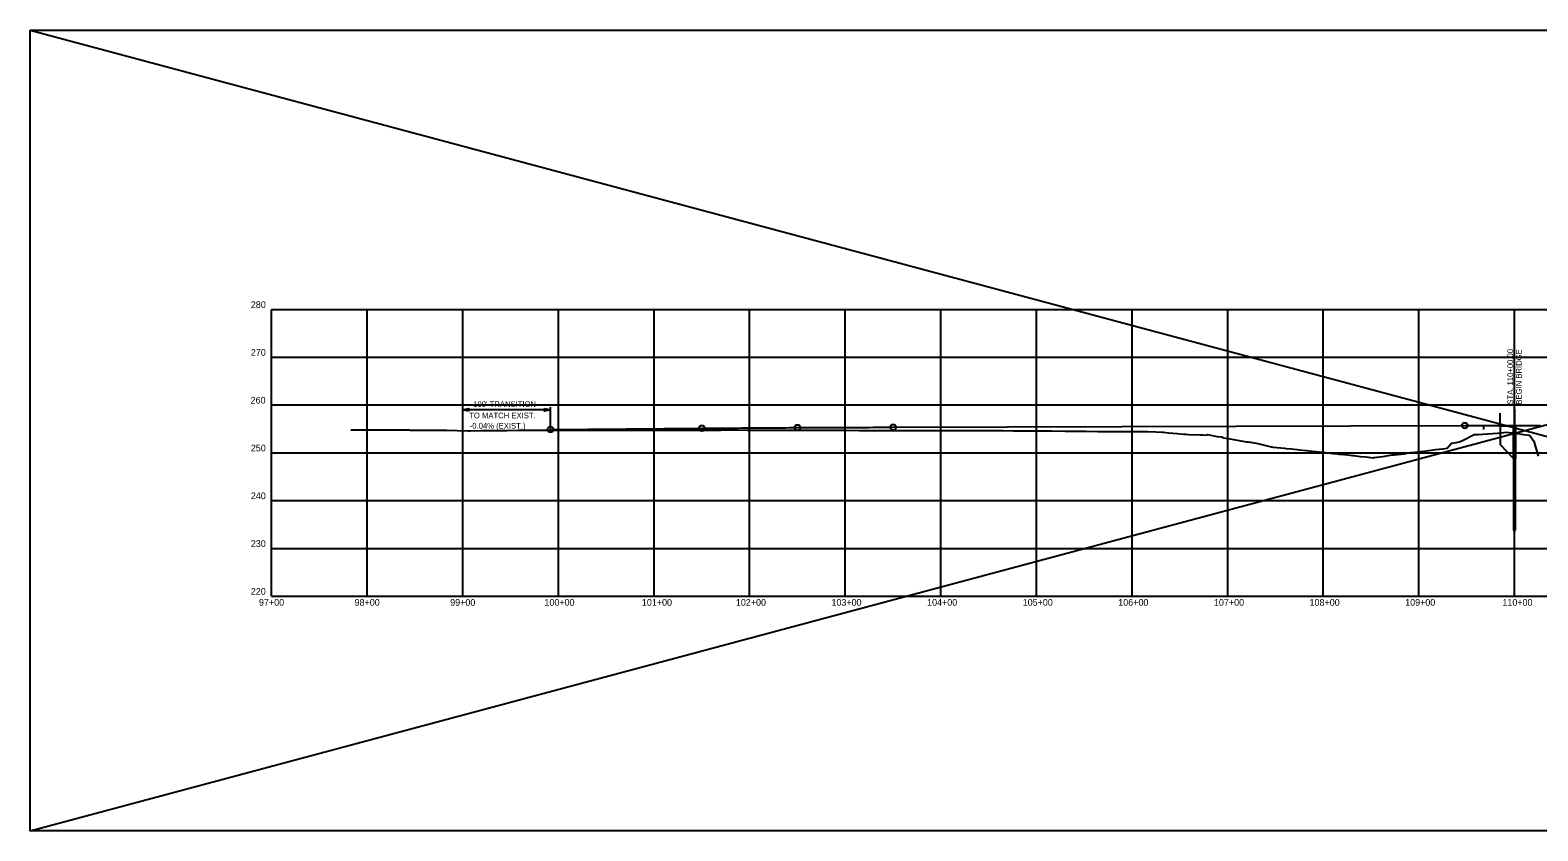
# Model space of a CAD drawing. Extents: x 1930770 to 1938778, y 596900 to 600561.
# Drawn here: x 1935653 to 1937230, y 598329 to 599167 of the extents above; entities that cross this region are included whole.
import ezdxf

# ---------------------------------------------------------------- set-up
doc = ezdxf.new("R2010")
doc.units = 0
for name, color, linetype in [('B_Centerline', 7, 'Continuous'), ('B_Pr_Beam_Line', 7, 'Continuous'), ('B_Pr_Columns', 7, 'Continuous'), ('B_Pr_Deck', 7, 'Continuous'), ('B_Pr_Rail', 7, 'Continuous'), ('Default', 7, 'Continuous'), ('S_CROSS_DRAIN_ANNOT', 7, 'Continuous'), ('S_DROP_INLET_ANNOT', 7, 'Continuous'), ('S_ELECTRIC_UTILITIES_ANNOT', 7, 'Continuous'), ('S_GAS_UTILITIES_ANNOT', 7, 'Continuous'), ('S_HIST_HIGH_WATER_ANNOT', 7, 'Continuous'), ('S_STORM_SEWER_ANNOT', 7, 'Continuous'), ('S_TELEPHONE_UTILITIES_ANNOT', 7, 'Continuous'), ('S_UTILITY_POLE_ANNOT', 7, 'Continuous'), ('S_WATER_UTILITIES_ANNOT', 7, 'Continuous')]:
    doc.layers.add(name, color=color, linetype=linetype)

msp = doc.modelspace()

# ---------------------------------------------------------------- linework, layer by layer
at = {"layer": 'B_Centerline'}
msp.add_line((1937205.2, 598631.1), (1937205.2, 598767.6), dxfattribs=at)
at = {"layer": 'B_Pr_Beam_Line'}
msp.add_line((1937204.7, 598748), (1937204.7, 598736.3), dxfattribs=at)
at = {"layer": 'B_Pr_Columns'}
for p, q in [((1937206.1, 598718.8), (1937204.4, 598718.8)), ((1937204.4, 598643.5), (1937204.4, 598718.8)), ((1937206.1, 598718.8), (1937204.4, 598718.8)), ((1937206.1, 598643.5), (1937206.1, 598718.8))]:
    msp.add_line(p, q, dxfattribs=at)
at = {"layer": 'B_Pr_Deck'}
msp.add_line((1937190.2, 598752.4), (1937205.2, 598752.7), dxfattribs=at)
msp.add_lwpolyline([(1937190.2, 598752.4), (1937190.2, 598733.4), (1937203.7, 598718.8)], dxfattribs=at)
at = {"layer": 'B_Pr_Rail'}
msp.add_line((1937205.2, 598770), (1937205.2, 598753.1), dxfattribs=at)
at = {"layer": 'Default'}
msp.add_line((1937205.2, 598643.5), (1937206.2, 598643.5), dxfattribs=at)
msp.add_lwpolyline([(1937203.9, 598643.5), (1937205, 598643.5), (1937205.2, 598644.9), (1937205, 598642.2), (1937205.2, 598643.5)], dxfattribs=at)
at = {"layer": 'S_CROSS_DRAIN_ANNOT'}
for p, q in [((1935905.2, 598574.6), (1935905.2, 598874.6)), ((1937105.2, 598824.6), (1937105.2, 598826.1)), ((1937105.2, 598824.6), (1937105.2, 598825.8)), ((1935905.2, 598574.6), (1938605.2, 598574.6))]:
    msp.add_line(p, q, dxfattribs=at)
msp.add_lwpolyline([(1935652.7, 599166.8), (1938778.1, 599166.8), (1938778.1, 598329.1), (1935652.7, 598329.1)], close=True, dxfattribs=at)
at = {"layer": 'S_ELECTRIC_UTILITIES_ANNOT'}
for p, q in [((1937205.2, 598782.6), (1937205.2, 598841.8)), ((1937205.2, 598752.6), (1937205.2, 598782.6))]:
    msp.add_line(p, q, dxfattribs=at)
for centre in [(1936196.8, 598749.1), (1936355.2, 598750.3), (1936455.2, 598751), (1936555.2, 598751.3), (1937153.2, 598753.1)]:
    msp.add_circle(centre, 3, dxfattribs=at)
at = {"layer": 'S_GAS_UTILITIES_ANNOT'}
msp.add_lwpolyline([(1937203.7, 598749.1), (1937203.7, 598718.8), (1937206.7, 598718.8), (1937206.7, 598752.7), (1937204.2, 598752.7), (1937204.2, 598749.1)], close=True, dxfattribs=at)
for points in [[(1937203.7, 598718.8), (1937206.7, 598718.8)], [(1937203.7, 598718.8), (1937206.7, 598718.8), (1937206.7, 598718.8)], [(1937203.7, 598718.8), (1937206.7, 598718.8), (1937206.7, 598718.8)]]:
    msp.add_lwpolyline(points, dxfattribs=at)
at = {"layer": 'S_HIST_HIGH_WATER_ANNOT'}
for p, q in [((1936196.8, 598749.1), (1936355.2, 598750.3)), ((1936555.2, 598751.3), (1937153.2, 598753.1))]:
    msp.add_line(p, q, dxfattribs=at)
for points in [[(1936355.2, 598750.3), (1936359.4, 598750.3), (1936363.6, 598750.3), (1936367.7, 598750.4), (1936371.9, 598750.4), (1936376.1, 598750.4), (1936380.2, 598750.5), (1936384.4, 598750.5), (1936388.6, 598750.5), (1936392.7, 598750.5), (1936396.9, 598750.6), (1936401.1, 598750.6), (1936405.2, 598750.6), (1936409.4, 598750.7), (1936413.6, 598750.7), (1936417.7, 598750.7), (1936421.9, 598750.7), (1936426.1, 598750.8), (1936430.2, 598750.8), (1936434.4, 598750.8), (1936438.6, 598750.8), (1936442.7, 598750.8), (1936446.9, 598750.9), (1936451.1, 598750.9), (1936459.4, 598750.9), (1936463.6, 598751), (1936467.7, 598751), (1936471.9, 598751), (1936476.1, 598751), (1936480.2, 598751), (1936484.4, 598751.1), (1936488.6, 598751.1), (1936492.7, 598751.1), (1936496.9, 598751.1), (1936501.1, 598751.1), (1936505.2, 598751.2), (1936509.4, 598751.2), (1936513.6, 598751.2), (1936517.7, 598751.2), (1936521.9, 598751.2), (1936526.1, 598751.2), (1936530.2, 598751.2), (1936534.4, 598751.3), (1936538.6, 598751.3), (1936542.7, 598751.3), (1936546.9, 598751.3), (1936551.1, 598751.3), (1936555.2, 598751.3)], [(1937153.2, 598753.1), (1937157.4, 598753.1), (1937161.6, 598753.1), (1937165.7, 598753.2), (1937169.9, 598753.2), (1937174.1, 598753.2), (1937178.2, 598753.2), (1937182.4, 598753.2), (1937186.6, 598753.2), (1937190.7, 598753.2), (1937194.9, 598753.2), (1937199.1, 598753.2), (1937203.2, 598753.2), (1937207.4, 598753.2), (1937211.6, 598753.2), (1937215.7, 598753.3), (1937219.9, 598753.3), (1937224.1, 598753.3), (1937228.2, 598753.3), (1937232.4, 598753.3)]]:
    msp.add_lwpolyline(points, dxfattribs=at)
at = {"layer": 'S_STORM_SEWER_ANNOT'}
for p, q in [((1936105.2, 598749.1), (1936105.2, 598772.5)), ((1936196.8, 598769.5), (1936105.2, 598769.5)), ((1936196.8, 598749.1), (1936196.8, 598772.5))]:
    msp.add_line(p, q, dxfattribs=at)
for points in [[(1936111.2, 598768), (1936105.2, 598769.5), (1936111.2, 598771)], [(1936190.8, 598771), (1936196.8, 598769.5), (1936190.8, 598768)]]:
    msp.add_lwpolyline(points, close=True, dxfattribs=at)
at = {"layer": 'S_TELEPHONE_UTILITIES_ANNOT'}
for p, q in [((1935652.7, 599166.8), (1938778.1, 598329.1)), ((1935652.7, 598329.1), (1938778.1, 599166.8)), ((1937190.2, 598752.4), (1937190.2, 598766.2)), ((1937205.2, 598752.6), (1937205.2, 598770)), ((1937173.2, 598748.9), (1937173.2, 598752.2))]:
    msp.add_line(p, q, dxfattribs=at)
at = {"layer": 'S_UTILITY_POLE_ANNOT'}
for p, q in [((1935905.2, 598874.6), (1938605.2, 598874.6)), ((1935905.2, 598874.6), (1938605.2, 598874.6)), ((1936005.2, 598574.6), (1936005.2, 598874.6)), ((1936105.2, 598574.6), (1936105.2, 598874.6)), ((1936205.2, 598574.6), (1936205.2, 598874.6)), ((1936305.2, 598574.6), (1936305.2, 598874.6)), ((1936405.2, 598574.6), (1936405.2, 598874.6)), ((1936505.2, 598574.6), (1936505.2, 598874.6)), ((1936605.2, 598574.6), (1936605.2, 598874.6)), ((1936705.2, 598574.6), (1936705.2, 598874.6)), ((1936805.2, 598574.6), (1936805.2, 598874.6)), ((1936905.2, 598574.6), (1936905.2, 598874.6)), ((1937005.2, 598574.6), (1937005.2, 598874.6)), ((1937105.2, 598574.6), (1937105.2, 598874.6)), ((1937205.2, 598574.6), (1937205.2, 598874.6)), ((1935905.2, 598824.6), (1938605.2, 598824.6)), ((1935905.2, 598774.6), (1938605.2, 598774.6)), ((1935905.2, 598724.6), (1938605.2, 598724.6)), ((1935905.2, 598674.6), (1938605.2, 598674.6)), ((1935905.2, 598624.6), (1938605.2, 598624.6))]:
    msp.add_line(p, q, dxfattribs=at)
at = {"layer": 'S_WATER_UTILITIES_ANNOT'}
msp.add_lwpolyline([(1935988.1, 598748.6), (1935990.4, 598748.6), (1935992.2, 598748.7), (1936010.8, 598748.6), (1936011.8, 598748.6), (1936023.7, 598748.6), (1936024.7, 598748.6), (1936036.6, 598748.5), (1936037.7, 598748.5), (1936049.6, 598748.5), (1936050.6, 598748.4), (1936062.5, 598748.4), (1936063.6, 598748.4), (1936086, 598748.1), (1936087.1, 598748.1), (1936088.2, 598748.1), (1936110.7, 598747.7), (1936111.8, 598747.7), (1936112.9, 598747.7), (1936124.6, 598747.8), (1936125.7, 598747.8), (1936137.5, 598747.9), (1936138.5, 598747.9), (1936150.4, 598748), (1936151.3, 598748), (1936163.2, 598748.1), (1936164.2, 598748.1), (1936177.5, 598748.1), (1936178.5, 598748.1), (1936191.7, 598748.2), (1936192.7, 598748.2), (1936196.8, 598748.2), (1936205.9, 598748.3), (1936207, 598748.3), (1936218.3, 598748.3), (1936220.1, 598748.3), (1936222.8, 598748.2), (1936223.1, 598748.2), (1936223.3, 598748.2), (1936224.1, 598748.2), (1936235.9, 598748.3), (1936236.8, 598748.3), (1936239.9, 598748.3), (1936248.4, 598748.2), (1936249.4, 598748.2), (1936260.9, 598748.2), (1936261.4, 598748.2), (1936262, 598748.2), (1936273.5, 598748.2), (1936274.6, 598748.2), (1936282.9, 598748.2), (1936286, 598748.2), (1936288.5, 598748.2), (1936304.5, 598748.2), (1936310.4, 598748.3), (1936313.2, 598748.3), (1936326, 598748.3), (1936334.7, 598748.3), (1936336.5, 598748.3), (1936347.5, 598748.4), (1936347.5, 598748.4), (1936349.4, 598748.4), (1936360.2, 598748.4), (1936362.3, 598748.4), (1936369.1, 598748.4), (1936373, 598748.4), (1936375.2, 598748.4), (1936385.8, 598748.5), (1936390.6, 598748.5), (1936402.8, 598748.4), (1936406.9, 598748.4), (1936412.1, 598748.4), (1936423.5, 598748.3), (1936428.1, 598748.3), (1936433.7, 598748.3), (1936444.2, 598748.3), (1936449.2, 598748.2), (1936455.2, 598748.2), (1936464.8, 598748.2), (1936470.4, 598748.2), (1936476.7, 598748.1), (1936477.5, 598748.1), (1936495.1, 598748.1), (1936498.3, 598748.1), (1936504, 598748.1), (1936519.8, 598748), (1936519.9, 598748), (1936530, 598748), (1936541.3, 598748), (1936543.2, 598748), (1936555.2, 598747.9), (1936562.9, 598747.9), (1936566.5, 598747.9), (1936572.9, 598747.9), (1936580.1, 598747.9), (1936584.4, 598747.9), (1936586, 598747.9), (1936593.8, 598747.8), (1936602.2, 598747.8), (1936605.9, 598747.8), (1936607.4, 598747.8), (1936616.4, 598747.8), (1936621, 598747.8), (1936627.5, 598747.8), (1936639, 598747.8), (1936645.4, 598747.8), (1936649, 598747.8), (1936665.4, 598747.8), (1936669.7, 598747.8), (1936670.5, 598747.8), (1936680.7, 598747.7), (1936682.3, 598747.7), (1936692.1, 598747.6), (1936693.8, 598747.6), (1936694.8, 598747.6), (1936706.9, 598747.5), (1936707.3, 598747.5), (1936713.6, 598747.5), (1936715.5, 598747.4), (1936719.8, 598747.4), (1936720.9, 598747.4), (1936735.1, 598747.3), (1936744.6, 598747.2), (1936752.7, 598747.2), (1936756.7, 598747.1), (1936769.4, 598747), (1936778.2, 598747), (1936783.5, 598746.9), (1936793.1, 598746.9), (1936799.7, 598746.8), (1936813.2, 598746.7), (1936816.9, 598746.7), (1936821.3, 598746.7), (1936830, 598746.6), (1936836.5, 598746.1), (1936838.4, 598746), (1936842.8, 598745.6), (1936843.1, 598745.6), (1936852.4, 598744.8), (1936859, 598744.2), (1936861.4, 598744), (1936864.3, 598743.9), (1936876.1, 598743.3), (1936878.9, 598743.5), (1936883.5, 598742.9), (1936884.3, 598743.7), (1936885.9, 598743.3), (1936889, 598742.7), (1936894.3, 598741.6), (1936898.7, 598741.4), (1936901.1, 598740.2), (1936905.6, 598739.5), (1936907.4, 598739.2), (1936925, 598736.2), (1936926.7, 598735.9), (1936927.9, 598735.8), (1936928.9, 598735.6), (1936936.7, 598734.2), (1936950.5, 598730.9), (1936951.3, 598730.7), (1936952.9, 598730.6), (1936964.6, 598729.4), (1936966.5, 598729.2), (1936972, 598728.6), (1936977.9, 598728), (1936980.3, 598727.8), (1936991.2, 598726.6), (1936993.5, 598726.4), (1936994, 598726.3), (1937004.5, 598725.1), (1937007.9, 598724.8), (1937015.1, 598724), (1937017.7, 598723.7), (1937021.8, 598723.3), (1937031, 598722.3), (1937035.8, 598721.8), (1937036.6, 598721.8), (1937044.2, 598720.8), (1937049.9, 598720.3), (1937057.5, 598719.4), (1937058.1, 598719.5), (1937067.6, 598720.6), (1937077.2, 598722.3), (1937079.7, 598722.6), (1937089.6, 598723.6), (1937096.5, 598724.8), (1937101.2, 598725.3), (1937110.2, 598726.3), (1937115.7, 598727.1), (1937122.6, 598727.9), (1937130.2, 598728.8), (1937134.8, 598729.5), (1937139.3, 598734.5), (1937144.1, 598735.3), (1937147.5, 598735.9), (1937151.5, 598737.9), (1937162.9, 598743.7), (1937163.7, 598743.7), (1937165.5, 598743.7), (1937166.9, 598743.6), (1937186.9, 598745.2), (1937188.1, 598745.3), (1937190.9, 598745.5), (1937197.2, 598746.2), (1937199.5, 598745.8), (1937204.5, 598745.4), (1937208.3, 598744.8), (1937214.7, 598743.9), (1937220.4, 598743.1), (1937221.1, 598742.6), (1937225.5, 598736.8), (1937229.8, 598721.2)], dxfattribs=at)

# ---------------------------------------------------------------- texts
at = {"layer": 'S_DROP_INLET_ANNOT'}
for s, height, p in [('280', 7, (1935883.5, 598876.1)), ('280', 7, (1935883.5, 598876.1)), ('270', 7, (1935883.5, 598826.1)), ('260', 7, (1935883.3, 598776.1)), ('250', 7, (1935883.5, 598726.1)), ('240', 7, (1935883.5, 598676.1)), ('230', 7, (1935883.5, 598626.1)), ('220', 7, (1935883.5, 598576.1)), ('97+00', 7, (1935892, 598564.6)), ('-', 0.0001, (1935905.2, 598574.6)), ('98+00', 7, (1935992, 598564.6)), ('99+00', 7, (1936092, 598564.6)), ('100+00', 7, (1936190.6, 598564.6)), ('101+00', 7, (1936292.5, 598564.6)), ('102+00', 7, (1936390.8, 598564.6)), ('103+00', 7, (1936490.8, 598564.6)), ('104+00', 7, (1936590.8, 598564.6)), ('105+00', 7, (1936690.8, 598564.6)), ('106+00', 7, (1936790.7, 598564.6)), ('107+00', 7, (1936890.8, 598564.6)), ('108+00', 7, (1936990.8, 598564.6)), ('109+00', 7, (1937090.8, 598564.6)), ('110+00', 7, (1937192.5, 598564.6))]:
    msp.add_text(s, height=height, dxfattribs=at).set_placement(p)
at = {"layer": 'S_ELECTRIC_UTILITIES_ANNOT'}
for s, rotation, p in [('STA. 110+00.00', 90, (1937203.7, 598775)), ('BEGIN BRIDGE', 90, (1937212.7, 598775)), ('-0.04% (EXIST.)', 359.8468, (1936112.4, 598749.9))]:
    msp.add_text(s, height=6, rotation=rotation, dxfattribs=at).set_placement(p)
at = {"layer": 'S_STORM_SEWER_ANNOT'}
for s, p in [('TO MATCH EXIST.', (1936111.9, 598760.6)), ("100' TRANSITION", (1936116.1, 598772.5))]:
    msp.add_text(s, height=6, rotation=0.0048, dxfattribs=at).set_placement(p)

doc.saveas('drawing.dxf')
